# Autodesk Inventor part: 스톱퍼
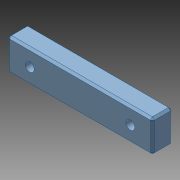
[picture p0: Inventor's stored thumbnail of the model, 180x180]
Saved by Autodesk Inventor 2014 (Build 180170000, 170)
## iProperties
Created: 2023-09
Part Number: 스톱퍼
Material: 강철, 탄소
Document SubType Name: Modeling
Designer: mdu-01
Density: 1 g/cm^3
Appearance: 기본값(1)
Author: mdu-01
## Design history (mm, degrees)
sketch "스케치1"
  geometry: L1 (-36, -8)-(36, -8); L2 (36, -8)-(36, 8); L3 (36, 8)-(-36, 8); L4 (-36, 8)-(-36, -8); L5 (-36, -8)-(36, 8); L6 (36, -8)-(-36, 8); 1 further point
  constraints: 12 end point, 2 midpoint, 2 parallel, 1 horizontal, 1 perpendicular
  dimensions: "d0" = 16 distance between parallel lines of L1 L3; "d2" = 72 distance between parallel lines of L2 L4
extrude "돌출1" new body sketch "스케치1" distance "d3" = 10; taper "d4" = 0 deg
sketch "스케치2"
  geometry: L1 (0, 0)-(0, -7.829); 2 further points
  constraints: 2 end point, 1 horizontal alignment, 1 symmetric about line, 1 vertical
  dimensions: "d5" = 50 distance of point (25, 0) point (-25, 0)
hole "구멍1" sketch "스케치2" at (-25, 0), (25, 0) diameter "d7" = 4.5; stored, may be unused: countersink angle "d11" = 90 deg, drill point angle "d13" = 118 deg; dims "d8" = 6, "d9" = 8, "d10" = 4.4, "d12" = 8
chamfer "모따기1" distance "d14" = 1; stored, may be unused: second distance "d15" = 2, angle "d16" = 45 deg
node "솔리드1"
